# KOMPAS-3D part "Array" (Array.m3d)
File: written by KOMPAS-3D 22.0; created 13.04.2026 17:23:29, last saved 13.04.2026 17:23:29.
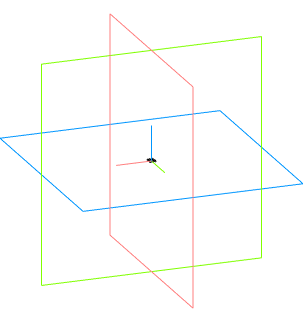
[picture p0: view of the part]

Document properties: Автор: Andrey; Полное имя файла: C:\Users\User1\Documents\Array.m3d

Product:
- Part/product: Array

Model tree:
1. Операция без истории:1
2. Операция без истории:2
3. Операция без истории:3
4. Операция без истории:4
5. Операция без истории:5
6. Операция без истории:6
7. Операция без истории:7
8. Операция без истории:8
9. Операция без истории:9
10. Операция без истории:10
11. Операция без истории:11
12. Операция без истории:12
13. Операция без истории:13
14. Операция без истории:14
15. Операция без истории:15
16. Операция без истории:16
17. Операция без истории:17
18. Операция без истории:18
19. Операция без истории:19
20. Операция без истории:20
